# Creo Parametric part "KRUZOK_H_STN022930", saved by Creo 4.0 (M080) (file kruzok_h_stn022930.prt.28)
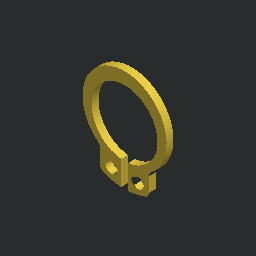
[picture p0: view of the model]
Units: Custom; MM, KILOGRAM, SECS
Materials in the file: OCEL_N

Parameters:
  NAZOV = "KRUZOK_H_STN022930"
  NORMA = "STN 02 2930"
  PTC_MATERIAL_NAME = "OCEL_N"

Other parameters: HMOTNOST, HUSTOTA, D3, D0, D1, D2, D10, D5, D12, D11, D14, D15, D13, D27, D29, D28

Created from: C022930.PRT

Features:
  1. datum plane "DTM1"
  2. protrusion
  3. round
  4. protrusion
  5. round

Other named items: COPIED_GROUP, COPIED_GROUP_1

Named dimensions: male_d2, male_d5, vetsi_d5

Layers: 1, 2, 3, 4, 5, 6, 7, 8, 9, 10, 11, 12, 13, 14, 15, 16, 17, 18, 19, 20, 21, 22, 23, 24, 25, 26, 27, 28, 29, 30, 31, 32, ROVINY

Family table entries: GENERIC, KRUZOK_H_D1_8, KRUZOK_H_STN022930, value(d_val), value(i_val), KRUZOK_H_D1_10, KRUZOK_H_STN022930, KRUZOK_H_D1_11, KRUZOK_H_STN022930, 2/%, KRUZOK_H_D1_12, KRUZOK_H_STN022930, 2/', KRUZOK_H_D1_13, KRUZOK_H_STN022930, KRUZOK_H_D1_14, KRUZOK_H_STN022930, KRUZOK_H_D1_15, KRUZOK_H_STN022930, KRUZOK_H_D1_16, KRUZOK_H_STN022930, KRUZOK_H_D1_17, KRUZOK_H_STN022930, KRUZOK_H_D1_18, KRUZOK_H_STN022930, 2/1, KRUZOK_H_D1_19, KRUZOK_H_STN022930, 2/2, KRUZOK_H_D1_20, KRUZOK_H_STN022930, 2/3, KRUZOK_H_D1_21, KRUZOK_H_STN022930, 2/4, KRUZOK_H_D1_22, KRUZOK_H_STN022930, 2/5, KRUZOK_H_D1_24, KRUZOK_H_STN022930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

Surfaces: 6 plane, 6 cylinder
